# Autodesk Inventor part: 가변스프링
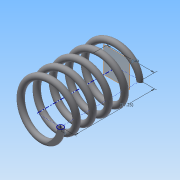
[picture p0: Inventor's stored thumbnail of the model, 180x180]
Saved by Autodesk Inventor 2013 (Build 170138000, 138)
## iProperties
Created: 2018-08
Part Number: 가변스프링
Material: 일반
Document SubType Name: Modeling
Designer: Administrator
Density: 1 g/cm^3
Mass: 12.1667 g
Surface Area: 98.6263 cm^2
Volume: 12.1667 cm^3
Author: Administrator
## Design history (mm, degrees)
sketch "스케치1"
  geometry: L1 (0, 0)-(20, 0); L2 (20, 0)-(20, 67.25); L3 (20, 67.25)-(0, 67.25); L4 (0, 67.25)-(0, 0); C1 r 2.5 at (20, 0)
  constraints: 8 end point, 2 parallel, 1 centre point, 1 coincident, 1 horizontal, 1 perpendicular
  dimensions: "d0" = 5 diameter of C1; "d2" = 67.25 distance between parallel lines of L3 L1 (derived); "d3" = 40 diameter of L2 L4
feature "코일1" pitch "d4" = 10; turns "d6" = 5; dims "d5" = 67.25 (= d2), "d7" = 0, angle "d8" = 90 deg, angle "d9" = 90 deg, "d10" = 0, "d11" = 0
sketch "스케치2"
  geometry: L1 (-22.5, 0)-(-17.5, 0) reference; 1 further point
  constraints: 1 horizontal alignment
extrude "돌출1" cut sketch "스케치2" stored distance "d12" = 10; taper "d13" = 0 deg
node "작업 평면1"
sketch "스케치3"
  geometry: L1 (22.5, 0)-(17.5, 0) reference; 1 further point
  constraints: 1 horizontal alignment
extrude "돌출2" cut sketch "스케치3" stored distance "d14" = 10; taper "d15" = 0 deg
node "솔리드1"
node "절단 모서리 투영1"
node "절단 모서리 투영2"
